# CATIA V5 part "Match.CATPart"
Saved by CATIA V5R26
Part number: Match
Bounding box of the stored display mesh (mm): x -80.825 to 220.996, y -154.06 to 514.937, z -58.81 to 90.824
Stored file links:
  D:\LinkedIn Learning\NURBS\CATIA\Class Parts\Match.CATPart
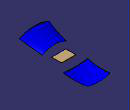
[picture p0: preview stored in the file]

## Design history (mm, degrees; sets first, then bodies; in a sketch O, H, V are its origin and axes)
AxisSystem1: origin (0, 0, 0), X (1, 0, 0), Y (0, 1, 0), Z (0, 0, 1)
Set1
  DatumSurface1 to DatumSurface3
Body1 (main body)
